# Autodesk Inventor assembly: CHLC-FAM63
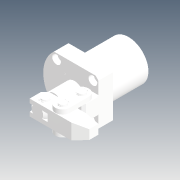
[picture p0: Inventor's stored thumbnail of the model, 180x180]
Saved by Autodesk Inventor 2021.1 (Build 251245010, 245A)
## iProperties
Created: 2019-04
Part Number: CHLC-FAM63
Description: STEP AP214
Document SubType Name: Assembly
Designer: user
Title: CHLC-FAM63.STEP
Revision Number: ÈÎºÎ
Sending System: SolidWorks 2016
Preprocessor: SwSTEP 2.0
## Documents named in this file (9)
- D:\Vault_2016\Projekty\Clamptek\Hydraulic\CHLC\CHLC-63\Inventor\CHLC-FAM63\CHLC-FAM63.iam
- D:\Vault_2016\Projekty\Clamptek\Hydraulic\CHLC\CHLC-63\Inventor\CHLC-FAM63\CHLC-FAM63BT_Ä¬ÈÏ[°´¼Ó¹¤].ipt
- D:\Vault_2016\Projekty\Clamptek\Hydraulic\CHLC\CHLC-63\Inventor\CHLC-FAM63\CHLC-63-02.ipt
- D:\Vault_2016\Projekty\Clamptek\Hydraulic\CHLC\CHLC-63\Inventor\CHLC-FAM63\CHLC-63-03.ipt
- D:\Vault_2016\Projekty\Clamptek\Hydraulic\CHLC\CHLC-63\Inventor\CHLC-FAM63\CHLC-63-04.ipt
- D:\Vault_2016\Projekty\Clamptek\Hydraulic\CHLC\CHLC-63\Inventor\CHLC-FAM63\CHLC-63-07.ipt
- D:\Vault_2016\Projekty\Clamptek\Hydraulic\CHLC\CHLC-63\Inventor\CHLC-FAM63\CHLC-63-01.ipt
- D:\Vault_2016\Projekty\Clamptek\Hydraulic\CHLC\CHLC-63\Inventor\CHLC-FAM63\CHLC-63-05.ipt
- D:\Vault_2016\Projekty\Clamptek\Hydraulic\CHLC\CHLC-63\Inventor\CHLC-FAM63\socket set screw flat point_iso_ISO 4026 - M5 x 6-S.ipt
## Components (18 placed, 18 different names)
1. CHLC-FAM63BT_Ä¬ÈÏ[°´¼Ó¹¤]_1
2. CHLC-63-02_2
3. CHLC-63-03_3
4. CHLC-63-04_4
5. CHLC-63-07_5
6. CHLC-63-04_6
7. CHLC-63-03_7
8. CHLC-63-07_8
9. CHLC-63-07_9
10. CHLC-63-07_10
11. CHLC-63-07_11
12. CHLC-63-01_12
13. CHLC-63-05_13
14. CHLC-63-07_14
15. socket set screw flat point_iso_ISO 4026 - M5 x 6-S_15
16. socket set screw flat point_iso_ISO 4026 - M5 x 6-S_16
17. socket set screw flat point_iso_ISO 4026 - M5 x 6-S_17
18. socket set screw flat point_iso_ISO 4026 - M5 x 6-S_18
